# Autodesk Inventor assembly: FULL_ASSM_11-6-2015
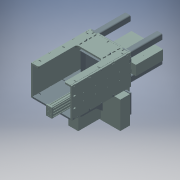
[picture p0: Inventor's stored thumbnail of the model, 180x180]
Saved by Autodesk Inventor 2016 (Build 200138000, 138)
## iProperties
Created: 2015-11
Part Number: FULL_ASSM_11-6-2015
Document SubType Name: Assembly
Designer: John
Title: FULL_ASSM_11-6-2015.stp
Sending System: SIEMENS PLM Software NX 7.5
Preprocessor: ST-DEVELOPER v11
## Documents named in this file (6)
- D:\3D Printer Designs\John Ledden Designs\DLP Printer\V0-4\FULL_ASSM_11-6-2015.iam
- D:\3D Printer Designs\John Ledden Designs\DLP Printer\V0-4\Mirror_ASSM.iam
- D:\3D Printer Designs\John Ledden Designs\DLP Printer\V0-4\C-Beam Linear Actuator 500mm.iam
- D:\3D Printer Designs\John Ledden Designs\DLP Printer\V0-4\Bed_ASSM.iam
- D:\3D Printer Designs\John Ledden Designs\DLP Printer\V0-4\Vat_ASSM.iam
- D:\3D Printer Designs\John Ledden Designs\DLP Printer\V0-4\Frame_ASSM.iam
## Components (5 placed, 5 different names)
1. Mirror_ASSM_1186 [sub-assembly]
2. C-Beam Linear Actuator 500mm_1187 [sub-assembly]
3. Bed_ASSM_1188 [sub-assembly]
4. Vat_ASSM_1189 [sub-assembly]
5. Frame_ASSM_1190 [sub-assembly]
